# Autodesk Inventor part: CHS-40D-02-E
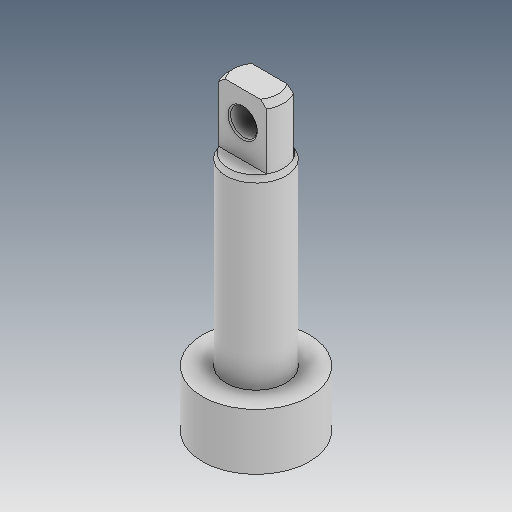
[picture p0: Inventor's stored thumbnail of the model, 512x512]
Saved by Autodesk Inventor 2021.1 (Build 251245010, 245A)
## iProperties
Created: 2019-04
Part Number: CHS-40D-02-E
Material: Ogólny
Document SubType Name: Modeling
Designer: user
Density: 1 g/cm^3
Appearance: Domyślna
Author: user
Revision Number: ÈÎºÎ
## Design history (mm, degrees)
feature "ÊäÈë1"
feature "ÊäÈë2"
node "Bryła1"
node "Bryła2"
